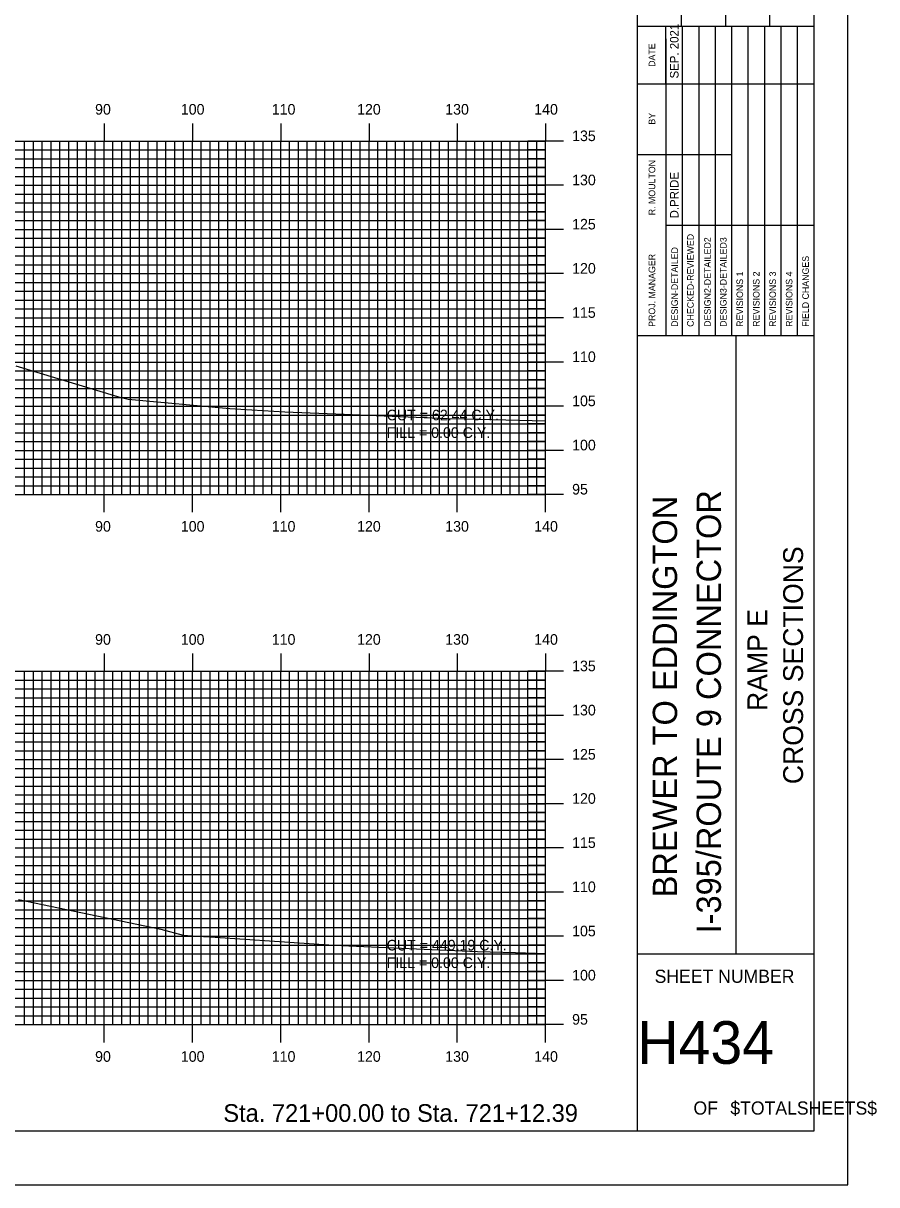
# Model space of a CAD drawing. Extents: x 858445 to 858788, y 364366 to 364586.
# Drawn here: x 858691.7 to 858788.4, y 364365.7 to 364497.1 of the extents above; entities that cross this region are included whole.
import ezdxf

# ---------------------------------------------------------------- set-up
doc = ezdxf.new("R2010")
doc.units = 0
for name, color, linetype in [('BORDER', 7, 'Continuous'), ('D_Text_Standard', 7, 'Continuous'), ('H_V ANNOTATION', 7, 'Continuous'), ('MAJOR', 7, 'Continuous'), ('MINOR', 7, 'Continuous'), ('PLOT BOUNDARY', 7, 'Continuous'), ('S_Roadway_Centerline', 7, 'Continuous')]:
    doc.layers.add(name, color=color, linetype=linetype)

msp = doc.modelspace()

# ---------------------------------------------------------------- linework, layer by layer
at = {"layer": 'BORDER'}
for p, q in [((858761.27, 364371.79), (858761.27, 364581.79)), ((858766.27, 364496.79), (858766.27, 364514.09)), ((858771.27, 364496.79), (858771.27, 364514.09)), ((858776.27, 364496.79), (858776.27, 364514.09)), ((858761.27, 364496.79), (858781.27, 364496.79)), ((858761.27, 364461.79), (858781.27, 364461.79)), ((858772.46, 364391.79), (858772.46, 364461.79)), ((858761.27, 364391.79), (858781.27, 364391.79))]:
    msp.add_line(p, q, dxfattribs=at)
msp.add_lwpolyline([(858461.27, 364371.79), (858781.27, 364371.79), (858781.27, 364581.79), (858461.27, 364581.79)], close=True, dxfattribs=at)
for points in [[(858764.5, 364490.29), (858764.5, 364496.79)], [(858766.37, 364461.8), (858766.37, 364496.79)], [(858768.23, 364496.79), (858768.23, 364461.8)], [(858770.1, 364461.8), (858770.1, 364496.79)], [(858771.96, 364461.8), (858771.96, 364496.79)], [(858773.82, 364461.8), (858773.82, 364496.79)], [(858775.69, 364461.8), (858775.69, 364496.79)], [(858777.55, 364461.8), (858777.55, 364496.79)], [(858779.41, 364461.8), (858779.41, 364496.79)], [(858764.51, 364461.8), (858764.51, 364495.38)], [(858761.27, 364490.29), (858781.27, 364490.29)], [(858761.27, 364482.29), (858764.51, 364482.29)], [(858764.5, 364482.29), (858771.96, 364482.29)], [(858764.5, 364474.29), (858781.27, 364474.29)]]:
    msp.add_lwpolyline(points, dxfattribs=at)
at = {"layer": 'MAJOR'}
for p, q in [((858700.87, 364485.79), (858700.87, 364483.79)), ((858710.87, 364485.79), (858710.87, 364483.79)), ((858720.87, 364485.79), (858720.87, 364483.79)), ((858730.87, 364485.79), (858730.87, 364483.79)), ((858740.87, 364485.79), (858740.87, 364483.79)), ((858750.87, 364485.79), (858750.87, 364483.79)), ((858470.87, 364483.79), (858750.87, 364483.79)), ((858470.87, 364483.79), (858750.87, 364483.79)), ((858700.87, 364443.79), (858700.87, 364483.79)), ((858710.87, 364443.79), (858710.87, 364483.79)), ((858720.87, 364443.79), (858720.87, 364483.79)), ((858730.87, 364443.79), (858730.87, 364483.79)), ((858740.87, 364443.79), (858740.87, 364483.79)), ((858752.88, 364483.79), (858748.87, 364483.79)), ((858750.87, 364443.79), (858750.87, 364483.79)), ((858750.87, 364443.79), (858750.87, 364483.79)), ((858470.87, 364478.79), (858750.87, 364478.79)), ((858752.88, 364478.79), (858748.87, 364478.79)), ((858470.87, 364473.79), (858750.87, 364473.79)), ((858752.88, 364473.79), (858748.87, 364473.79)), ((858470.87, 364468.79), (858750.87, 364468.79)), ((858752.88, 364468.79), (858748.87, 364468.79)), ((858470.87, 364463.79), (858750.87, 364463.79)), ((858752.88, 364463.79), (858748.87, 364463.79)), ((858470.87, 364458.79), (858750.87, 364458.79)), ((858752.88, 364458.79), (858748.87, 364458.79)), ((858470.87, 364453.79), (858750.87, 364453.79)), ((858752.88, 364453.79), (858748.87, 364453.79)), ((858470.87, 364448.79), (858750.87, 364448.79)), ((858752.88, 364448.79), (858748.87, 364448.79)), ((858470.87, 364443.79), (858750.87, 364443.79)), ((858470.87, 364443.79), (858750.87, 364443.79)), ((858700.87, 364441.78), (858700.87, 364443.79)), ((858710.87, 364441.78), (858710.87, 364443.79)), ((858720.87, 364441.78), (858720.87, 364443.79)), ((858730.87, 364441.78), (858730.87, 364443.79)), ((858740.87, 364441.78), (858740.87, 364443.79)), ((858752.88, 364443.79), (858748.87, 364443.79)), ((858750.87, 364441.78), (858750.87, 364443.79)), ((858700.87, 364425.79), (858700.87, 364423.79)), ((858710.87, 364425.79), (858710.87, 364423.79)), ((858720.87, 364425.79), (858720.87, 364423.79)), ((858730.87, 364425.79), (858730.87, 364423.79)), ((858740.87, 364425.79), (858740.87, 364423.79)), ((858750.87, 364425.79), (858750.87, 364423.79)), ((858470.87, 364423.79), (858750.87, 364423.79)), ((858470.87, 364423.79), (858750.87, 364423.79)), ((858700.87, 364383.79), (858700.87, 364423.79)), ((858710.87, 364383.79), (858710.87, 364423.79)), ((858720.87, 364383.79), (858720.87, 364423.79)), ((858730.87, 364383.79), (858730.87, 364423.79)), ((858740.87, 364383.79), (858740.87, 364423.79)), ((858752.88, 364423.79), (858748.87, 364423.79)), ((858750.87, 364383.79), (858750.87, 364423.79)), ((858750.87, 364383.79), (858750.87, 364423.79)), ((858470.87, 364418.79), (858750.87, 364418.79)), ((858752.88, 364418.79), (858748.87, 364418.79)), ((858470.87, 364413.79), (858750.87, 364413.79)), ((858752.88, 364413.79), (858748.87, 364413.79)), ((858470.87, 364408.79), (858750.87, 364408.79)), ((858752.88, 364408.79), (858748.87, 364408.79)), ((858470.87, 364403.79), (858750.87, 364403.79)), ((858752.88, 364403.79), (858748.87, 364403.79)), ((858470.87, 364398.79), (858750.87, 364398.79)), ((858752.88, 364398.79), (858748.87, 364398.79)), ((858470.87, 364393.79), (858750.87, 364393.79)), ((858752.88, 364393.79), (858748.87, 364393.79)), ((858470.87, 364388.79), (858750.87, 364388.79)), ((858752.88, 364388.79), (858748.87, 364388.79)), ((858470.87, 364383.79), (858750.87, 364383.79)), ((858470.87, 364383.79), (858750.87, 364383.79)), ((858700.87, 364381.78), (858700.87, 364383.79)), ((858710.87, 364381.78), (858710.87, 364383.79)), ((858720.87, 364381.78), (858720.87, 364383.79)), ((858730.87, 364381.78), (858730.87, 364383.79)), ((858740.87, 364381.78), (858740.87, 364383.79)), ((858752.88, 364383.79), (858748.87, 364383.79)), ((858750.87, 364381.78), (858750.87, 364383.79))]:
    msp.add_line(p, q, dxfattribs=at)
at = {"layer": 'MINOR'}
for p, q in [((858691.87, 364443.79), (858691.87, 364483.79)), ((858692.87, 364443.79), (858692.87, 364483.79)), ((858693.87, 364443.79), (858693.87, 364483.79)), ((858694.87, 364443.79), (858694.87, 364483.79)), ((858695.87, 364443.79), (858695.87, 364483.79)), ((858696.87, 364443.79), (858696.87, 364483.79)), ((858697.87, 364443.79), (858697.87, 364483.79)), ((858698.87, 364443.79), (858698.87, 364483.79)), ((858699.87, 364443.79), (858699.87, 364483.79)), ((858701.87, 364443.79), (858701.87, 364483.79)), ((858702.87, 364443.79), (858702.87, 364483.79)), ((858703.87, 364443.79), (858703.87, 364483.79)), ((858704.87, 364443.79), (858704.87, 364483.79)), ((858705.87, 364443.79), (858705.87, 364483.79)), ((858706.87, 364443.79), (858706.87, 364483.79)), ((858707.87, 364443.79), (858707.87, 364483.79)), ((858708.87, 364443.79), (858708.87, 364483.79)), ((858709.87, 364443.79), (858709.87, 364483.79)), ((858711.87, 364443.79), (858711.87, 364483.79)), ((858712.87, 364443.79), (858712.87, 364483.79)), ((858713.87, 364443.79), (858713.87, 364483.79)), ((858714.87, 364443.79), (858714.87, 364483.79)), ((858715.87, 364443.79), (858715.87, 364483.79)), ((858716.87, 364443.79), (858716.87, 364483.79)), ((858717.87, 364443.79), (858717.87, 364483.79)), ((858718.87, 364443.79), (858718.87, 364483.79)), ((858719.87, 364443.79), (858719.87, 364483.79)), ((858721.87, 364443.79), (858721.87, 364483.79)), ((858722.87, 364443.79), (858722.87, 364483.79)), ((858723.87, 364443.79), (858723.87, 364483.79)), ((858724.87, 364443.79), (858724.87, 364483.79)), ((858725.87, 364443.79), (858725.87, 364483.79)), ((858726.87, 364443.79), (858726.87, 364483.79)), ((858727.87, 364443.79), (858727.87, 364483.79)), ((858728.87, 364443.79), (858728.87, 364483.79)), ((858729.87, 364443.79), (858729.87, 364483.79)), ((858731.87, 364443.79), (858731.87, 364483.79)), ((858732.87, 364443.79), (858732.87, 364483.79)), ((858733.87, 364443.79), (858733.87, 364483.79)), ((858734.87, 364443.79), (858734.87, 364483.79)), ((858735.87, 364443.79), (858735.87, 364483.79)), ((858736.87, 364443.79), (858736.87, 364483.79)), ((858737.87, 364443.79), (858737.87, 364483.79)), ((858738.87, 364443.79), (858738.87, 364483.79)), ((858739.87, 364443.79), (858739.87, 364483.79)), ((858741.87, 364443.79), (858741.87, 364483.79)), ((858742.87, 364443.79), (858742.87, 364483.79)), ((858743.87, 364443.79), (858743.87, 364483.79)), ((858744.87, 364443.79), (858744.87, 364483.79)), ((858745.87, 364443.79), (858745.87, 364483.79)), ((858746.87, 364443.79), (858746.87, 364483.79)), ((858747.87, 364443.79), (858747.87, 364483.79)), ((858748.87, 364443.79), (858748.87, 364483.79)), ((858749.87, 364443.79), (858749.87, 364483.79)), ((858470.87, 364482.79), (858750.87, 364482.79)), ((858470.87, 364481.79), (858750.87, 364481.79)), ((858750.87, 364482.79), (858748.87, 364482.79)), ((858750.87, 364481.79), (858748.87, 364481.79)), ((858470.87, 364480.79), (858750.87, 364480.79)), ((858750.87, 364480.79), (858748.87, 364480.79)), ((858470.87, 364479.79), (858750.87, 364479.79)), ((858750.87, 364479.79), (858748.87, 364479.79)), ((858470.87, 364477.79), (858750.87, 364477.79)), ((858750.87, 364477.79), (858748.87, 364477.79)), ((858470.87, 364476.79), (858750.87, 364476.79)), ((858750.87, 364476.79), (858748.87, 364476.79)), ((858470.87, 364475.79), (858750.87, 364475.79)), ((858750.87, 364475.79), (858748.87, 364475.79)), ((858470.87, 364474.79), (858750.87, 364474.79)), ((858750.87, 364474.79), (858748.87, 364474.79)), ((858470.87, 364472.79), (858750.87, 364472.79)), ((858750.87, 364472.79), (858748.87, 364472.79)), ((858470.87, 364471.79), (858750.87, 364471.79)), ((858750.87, 364471.79), (858748.87, 364471.79)), ((858470.87, 364470.79), (858750.87, 364470.79)), ((858750.87, 364470.79), (858748.87, 364470.79)), ((858470.87, 364469.79), (858750.87, 364469.79)), ((858750.87, 364469.79), (858748.87, 364469.79)), ((858470.87, 364467.79), (858750.87, 364467.79)), ((858750.87, 364467.79), (858748.87, 364467.79)), ((858470.87, 364466.79), (858750.87, 364466.79)), ((858750.87, 364466.79), (858748.87, 364466.79)), ((858470.87, 364465.79), (858750.87, 364465.79)), ((858470.87, 364464.79), (858750.87, 364464.79)), ((858750.87, 364465.79), (858748.87, 364465.79)), ((858750.87, 364464.79), (858748.87, 364464.79)), ((858470.87, 364462.79), (858750.87, 364462.79)), ((858750.87, 364462.79), (858748.87, 364462.79)), ((858470.87, 364461.79), (858750.87, 364461.79)), ((858470.87, 364460.79), (858750.87, 364460.79)), ((858750.87, 364461.79), (858748.87, 364461.79)), ((858750.87, 364460.79), (858748.87, 364460.79)), ((858470.87, 364459.79), (858750.87, 364459.79)), ((858750.87, 364459.79), (858748.87, 364459.79)), ((858470.87, 364457.79), (858750.87, 364457.79)), ((858470.87, 364456.79), (858750.87, 364456.79)), ((858750.87, 364457.79), (858748.87, 364457.79)), ((858750.87, 364456.79), (858748.87, 364456.79)), ((858470.87, 364455.79), (858750.87, 364455.79)), ((858750.87, 364455.79), (858748.87, 364455.79)), ((858470.87, 364454.79), (858750.87, 364454.79)), ((858750.87, 364454.79), (858748.87, 364454.79)), ((858470.87, 364452.79), (858750.87, 364452.79)), ((858750.87, 364452.79), (858748.87, 364452.79)), ((858470.87, 364451.79), (858750.87, 364451.79)), ((858750.87, 364451.79), (858748.87, 364451.79)), ((858470.87, 364450.79), (858750.87, 364450.79)), ((858750.87, 364450.79), (858748.87, 364450.79)), ((858470.87, 364449.79), (858750.87, 364449.79)), ((858750.87, 364449.79), (858748.87, 364449.79)), ((858470.87, 364447.79), (858750.87, 364447.79)), ((858750.87, 364447.79), (858748.87, 364447.79)), ((858470.87, 364446.79), (858750.87, 364446.79)), ((858750.87, 364446.79), (858748.87, 364446.79)), ((858470.87, 364445.79), (858750.87, 364445.79)), ((858750.87, 364445.79), (858748.87, 364445.79)), ((858470.87, 364444.79), (858750.87, 364444.79)), ((858750.87, 364444.79), (858748.87, 364444.79)), ((858470.87, 364422.79), (858750.87, 364422.79)), ((858691.87, 364383.79), (858691.87, 364423.79)), ((858692.87, 364383.79), (858692.87, 364423.79)), ((858693.87, 364383.79), (858693.87, 364423.79)), ((858694.87, 364383.79), (858694.87, 364423.79)), ((858695.87, 364383.79), (858695.87, 364423.79)), ((858696.87, 364383.79), (858696.87, 364423.79)), ((858697.87, 364383.79), (858697.87, 364423.79)), ((858698.87, 364383.79), (858698.87, 364423.79)), ((858699.87, 364383.79), (858699.87, 364423.79)), ((858701.87, 364383.79), (858701.87, 364423.79)), ((858702.87, 364383.79), (858702.87, 364423.79)), ((858703.87, 364383.79), (858703.87, 364423.79)), ((858704.87, 364383.79), (858704.87, 364423.79)), ((858705.87, 364383.79), (858705.87, 364423.79)), ((858706.87, 364383.79), (858706.87, 364423.79)), ((858707.87, 364383.79), (858707.87, 364423.79)), ((858708.87, 364383.79), (858708.87, 364423.79)), ((858709.87, 364383.79), (858709.87, 364423.79)), ((858711.87, 364383.79), (858711.87, 364423.79)), ((858712.87, 364383.79), (858712.87, 364423.79)), ((858713.87, 364383.79), (858713.87, 364423.79)), ((858714.87, 364383.79), (858714.87, 364423.79)), ((858715.87, 364383.79), (858715.87, 364423.79)), ((858716.87, 364383.79), (858716.87, 364423.79)), ((858717.87, 364383.79), (858717.87, 364423.79)), ((858718.87, 364383.79), (858718.87, 364423.79)), ((858719.87, 364383.79), (858719.87, 364423.79)), ((858721.87, 364383.79), (858721.87, 364423.79)), ((858722.87, 364383.79), (858722.87, 364423.79)), ((858723.87, 364383.79), (858723.87, 364423.79)), ((858724.87, 364383.79), (858724.87, 364423.79)), ((858725.87, 364383.79), (858725.87, 364423.79)), ((858726.87, 364383.79), (858726.87, 364423.79)), ((858727.87, 364383.79), (858727.87, 364423.79)), ((858728.87, 364383.79), (858728.87, 364423.79)), ((858729.87, 364383.79), (858729.87, 364423.79)), ((858731.87, 364383.79), (858731.87, 364423.79)), ((858732.87, 364383.79), (858732.87, 364423.79)), ((858733.87, 364383.79), (858733.87, 364423.79)), ((858734.87, 364383.79), (858734.87, 364423.79)), ((858735.87, 364383.79), (858735.87, 364423.79)), ((858736.87, 364383.79), (858736.87, 364423.79)), ((858737.87, 364383.79), (858737.87, 364423.79)), ((858738.87, 364383.79), (858738.87, 364423.79)), ((858739.87, 364383.79), (858739.87, 364423.79)), ((858741.87, 364383.79), (858741.87, 364423.79)), ((858742.87, 364383.79), (858742.87, 364423.79)), ((858743.87, 364383.79), (858743.87, 364423.79)), ((858744.87, 364383.79), (858744.87, 364423.79)), ((858745.87, 364383.79), (858745.87, 364423.79)), ((858746.87, 364383.79), (858746.87, 364423.79)), ((858747.87, 364383.79), (858747.87, 364423.79)), ((858748.87, 364383.79), (858748.87, 364423.79)), ((858750.87, 364422.79), (858748.87, 364422.79)), ((858749.87, 364383.79), (858749.87, 364423.79)), ((858470.87, 364421.79), (858750.87, 364421.79)), ((858750.87, 364421.79), (858748.87, 364421.79)), ((858470.87, 364420.79), (858750.87, 364420.79)), ((858750.87, 364420.79), (858748.87, 364420.79)), ((858470.87, 364419.79), (858750.87, 364419.79)), ((858750.87, 364419.79), (858748.87, 364419.79)), ((858470.87, 364417.79), (858750.87, 364417.79)), ((858750.87, 364417.79), (858748.87, 364417.79)), ((858470.87, 364416.79), (858750.87, 364416.79)), ((858750.87, 364416.79), (858748.87, 364416.79)), ((858470.87, 364415.79), (858750.87, 364415.79)), ((858470.87, 364414.79), (858750.87, 364414.79)), ((858750.87, 364415.79), (858748.87, 364415.79)), ((858750.87, 364414.79), (858748.87, 364414.79)), ((858470.87, 364412.79), (858750.87, 364412.79)), ((858750.87, 364412.79), (858748.87, 364412.79)), ((858470.87, 364411.79), (858750.87, 364411.79)), ((858470.87, 364410.79), (858750.87, 364410.79)), ((858750.87, 364411.79), (858748.87, 364411.79)), ((858750.87, 364410.79), (858748.87, 364410.79)), ((858470.87, 364409.79), (858750.87, 364409.79)), ((858750.87, 364409.79), (858748.87, 364409.79)), ((858470.87, 364407.79), (858750.87, 364407.79)), ((858470.87, 364406.79), (858750.87, 364406.79)), ((858750.87, 364407.79), (858748.87, 364407.79)), ((858750.87, 364406.79), (858748.87, 364406.79)), ((858470.87, 364405.79), (858750.87, 364405.79)), ((858750.87, 364405.79), (858748.87, 364405.79)), ((858470.87, 364404.79), (858750.87, 364404.79)), ((858750.87, 364404.79), (858748.87, 364404.79)), ((858470.87, 364402.79), (858750.87, 364402.79)), ((858470.87, 364401.79), (858750.87, 364401.79)), ((858750.87, 364402.79), (858748.87, 364402.79)), ((858750.87, 364401.79), (858748.87, 364401.79)), ((858470.87, 364400.79), (858750.87, 364400.79)), ((858750.87, 364400.79), (858748.87, 364400.79)), ((858470.87, 364399.79), (858750.87, 364399.79)), ((858750.87, 364399.79), (858748.87, 364399.79)), ((858470.87, 364397.79), (858750.87, 364397.79)), ((858750.87, 364397.79), (858748.87, 364397.79)), ((858470.87, 364396.79), (858750.87, 364396.79)), ((858750.87, 364396.79), (858748.87, 364396.79)), ((858470.87, 364395.79), (858750.87, 364395.79)), ((858750.87, 364395.79), (858748.87, 364395.79)), ((858470.87, 364394.79), (858750.87, 364394.79)), ((858750.87, 364394.79), (858748.87, 364394.79)), ((858470.87, 364392.79), (858750.87, 364392.79)), ((858750.87, 364392.79), (858748.87, 364392.79)), ((858470.87, 364391.79), (858750.87, 364391.79)), ((858750.87, 364391.79), (858748.87, 364391.79)), ((858470.87, 364390.79), (858750.87, 364390.79)), ((858470.87, 364389.79), (858750.87, 364389.79)), ((858750.87, 364390.79), (858748.87, 364390.79)), ((858750.87, 364389.79), (858748.87, 364389.79)), ((858470.87, 364387.79), (858750.87, 364387.79)), ((858750.87, 364387.79), (858748.87, 364387.79)), ((858470.87, 364386.79), (858750.87, 364386.79)), ((858470.87, 364385.79), (858750.87, 364385.79)), ((858750.87, 364386.79), (858748.87, 364386.79)), ((858750.87, 364385.79), (858748.87, 364385.79)), ((858470.87, 364384.79), (858750.87, 364384.79)), ((858750.87, 364384.79), (858748.87, 364384.79))]:
    msp.add_line(p, q, dxfattribs=at)
at = {"layer": 'PLOT BOUNDARY'}
msp.add_lwpolyline([(858445.09, 364365.67), (858785.09, 364365.67), (858785.09, 364585.67), (858445.09, 364585.67)], close=True, dxfattribs=at)
at = {"layer": 'S_Roadway_Centerline'}
for points in [[(858690.87, 364458.35), (858702.38, 364454.9), (858703.58, 364454.58), (858715.11, 364453.52), (858721.34, 364453.15), (858728.05, 364452.88), (858738.93, 364452.43), (858739.72, 364452.39), (858741.87, 364452.36), (858750.87, 364452.14)], [(858691.16, 364397.94), (858707.28, 364394.6), (858709.84, 364393.93), (858710.79, 364393.84), (858713.43, 364393.68), (858726.87, 364392.79), (858733.69, 364392.5), (858743.15, 364392.07), (858747.45, 364391.96), (858750.87, 364391.83)]]:
    msp.add_lwpolyline(points, dxfattribs=at)

# ---------------------------------------------------------------- texts
at = {"layer": 'BORDER'}
for s, height, p in [('SEP. 2021', 0.969, (858765.92, 364490.88)), ('DATE', 0.743, (858763.28, 364492.2)), ('BY', 0.743, (858763.28, 364485.66)), ('R. MOULTON', 0.745, (858763.28, 364475.4)), ('D.PRIDE', 0.969, (858765.92, 364475.04)), ('CHECKED-REVIEWED', 0.7455, (858767.64, 364462.77)), ('DESIGN2-DETAILED2', 0.7455, (858769.57, 364462.77)), ('DESIGN3-DETAILED3', 0.7455, (858771.36, 364462.77)), ('DESIGN-DETAILED', 0.7455, (858765.85, 364462.77)), ('PROJ. MANAGER', 0.7455, (858763.28, 364462.77)), ('FIELD CHANGES', 0.7455, (858780.68, 364462.77)), ('REVISIONS 1', 0.7455, (858773.23, 364462.77)), ('REVISIONS 2', 0.7455, (858775.09, 364462.77)), ('REVISIONS 3', 0.7455, (858776.95, 364462.77)), ('REVISIONS 4', 0.7455, (858778.82, 364462.77)), ('I-395/ROUTE 9 CONNECTOR', 2.7557, (858770.72, 364394.12)), ('BREWER TO EDDINGTON', 2.7557, (858765.76, 364398.2)), ('CROSS SECTIONS', 2.25, (858780.02, 364411.01)), ('RAMP E', 2.25, (858775.97, 364419.29))]:
    msp.add_text(s, height=height, rotation=90, dxfattribs=at).set_placement(p)
for s, height, p in [('SHEET NUMBER', 1.4905, (858763.21, 364388.52)), ('H434', 4.839, (858761.26, 364379.35)), ('$TOTALSHEETS$', 1.4905, (858771.79, 364373.61)), ('OF', 1.491, (858767.61, 364373.61))]:
    msp.add_text(s, height=height, dxfattribs=at).set_placement(p)
at = {"layer": 'D_Text_Standard'}
for s, p in [('CUT = 62.44 C.Y.', (858732.87, 364452.19)), ('FILL = 0.00 C.Y.', (858732.87, 364450.2)), ('CUT = 449.19 C.Y.', (858732.87, 364392.19)), ('FILL = 0.00 C.Y.', (858732.87, 364390.2))]:
    msp.add_text(s, height=1.2, dxfattribs=at).set_placement(p)
at = {"layer": 'H_V ANNOTATION'}
for s, height, p in [('90', 1.2, (858699.85, 364486.79)), ('100', 1.2, (858709.56, 364486.79)), ('110', 1.2, (858719.86, 364486.79)), ('120', 1.2, (858729.52, 364486.79)), ('130', 1.2, (858739.5, 364486.79)), ('140', 1.2, (858749.58, 364486.79)), ('135', 1.2, (858753.87, 364483.79)), ('130', 1.2, (858753.87, 364478.79)), ('125', 1.2, (858753.87, 364473.79)), ('120', 1.2, (858753.87, 364468.79)), ('115', 1.2, (858753.87, 364463.79)), ('110', 1.2, (858753.87, 364458.79)), ('105', 1.2, (858753.87, 364453.79)), ('100', 1.2, (858753.87, 364448.79)), ('95', 1.2, (858753.87, 364443.79)), ('90', 1.2, (858699.85, 364439.59)), ('100', 1.2, (858709.56, 364439.59)), ('110', 1.2, (858719.86, 364439.59)), ('120', 1.2, (858729.52, 364439.59)), ('130', 1.2, (858739.5, 364439.59)), ('140', 1.2, (858749.58, 364439.59)), ('90', 1.2, (858699.85, 364426.79)), ('100', 1.2, (858709.56, 364426.79)), ('110', 1.2, (858719.86, 364426.79)), ('120', 1.2, (858729.52, 364426.79)), ('130', 1.2, (858739.5, 364426.79)), ('140', 1.2, (858749.58, 364426.79)), ('135', 1.2, (858753.87, 364423.79)), ('130', 1.2, (858753.87, 364418.79)), ('125', 1.2, (858753.87, 364413.79)), ('120', 1.2, (858753.87, 364408.79)), ('115', 1.2, (858753.87, 364403.79)), ('110', 1.2, (858753.87, 364398.79)), ('105', 1.2, (858753.87, 364393.79)), ('100', 1.2, (858753.87, 364388.79)), ('95', 1.2, (858753.87, 364383.79)), ('90', 1.2, (858699.85, 364379.59)), ('100', 1.2, (858709.56, 364379.59)), ('110', 1.2, (858719.86, 364379.59)), ('120', 1.2, (858729.52, 364379.59)), ('130', 1.2, (858739.5, 364379.59)), ('140', 1.2, (858749.58, 364379.59)), ('Sta. 721+00.00 to Sta. 721+12.39', 2.0004, (858714.37, 364372.79))]:
    msp.add_text(s, height=height, dxfattribs=at).set_placement(p)

doc.saveas('drawing.dxf')
